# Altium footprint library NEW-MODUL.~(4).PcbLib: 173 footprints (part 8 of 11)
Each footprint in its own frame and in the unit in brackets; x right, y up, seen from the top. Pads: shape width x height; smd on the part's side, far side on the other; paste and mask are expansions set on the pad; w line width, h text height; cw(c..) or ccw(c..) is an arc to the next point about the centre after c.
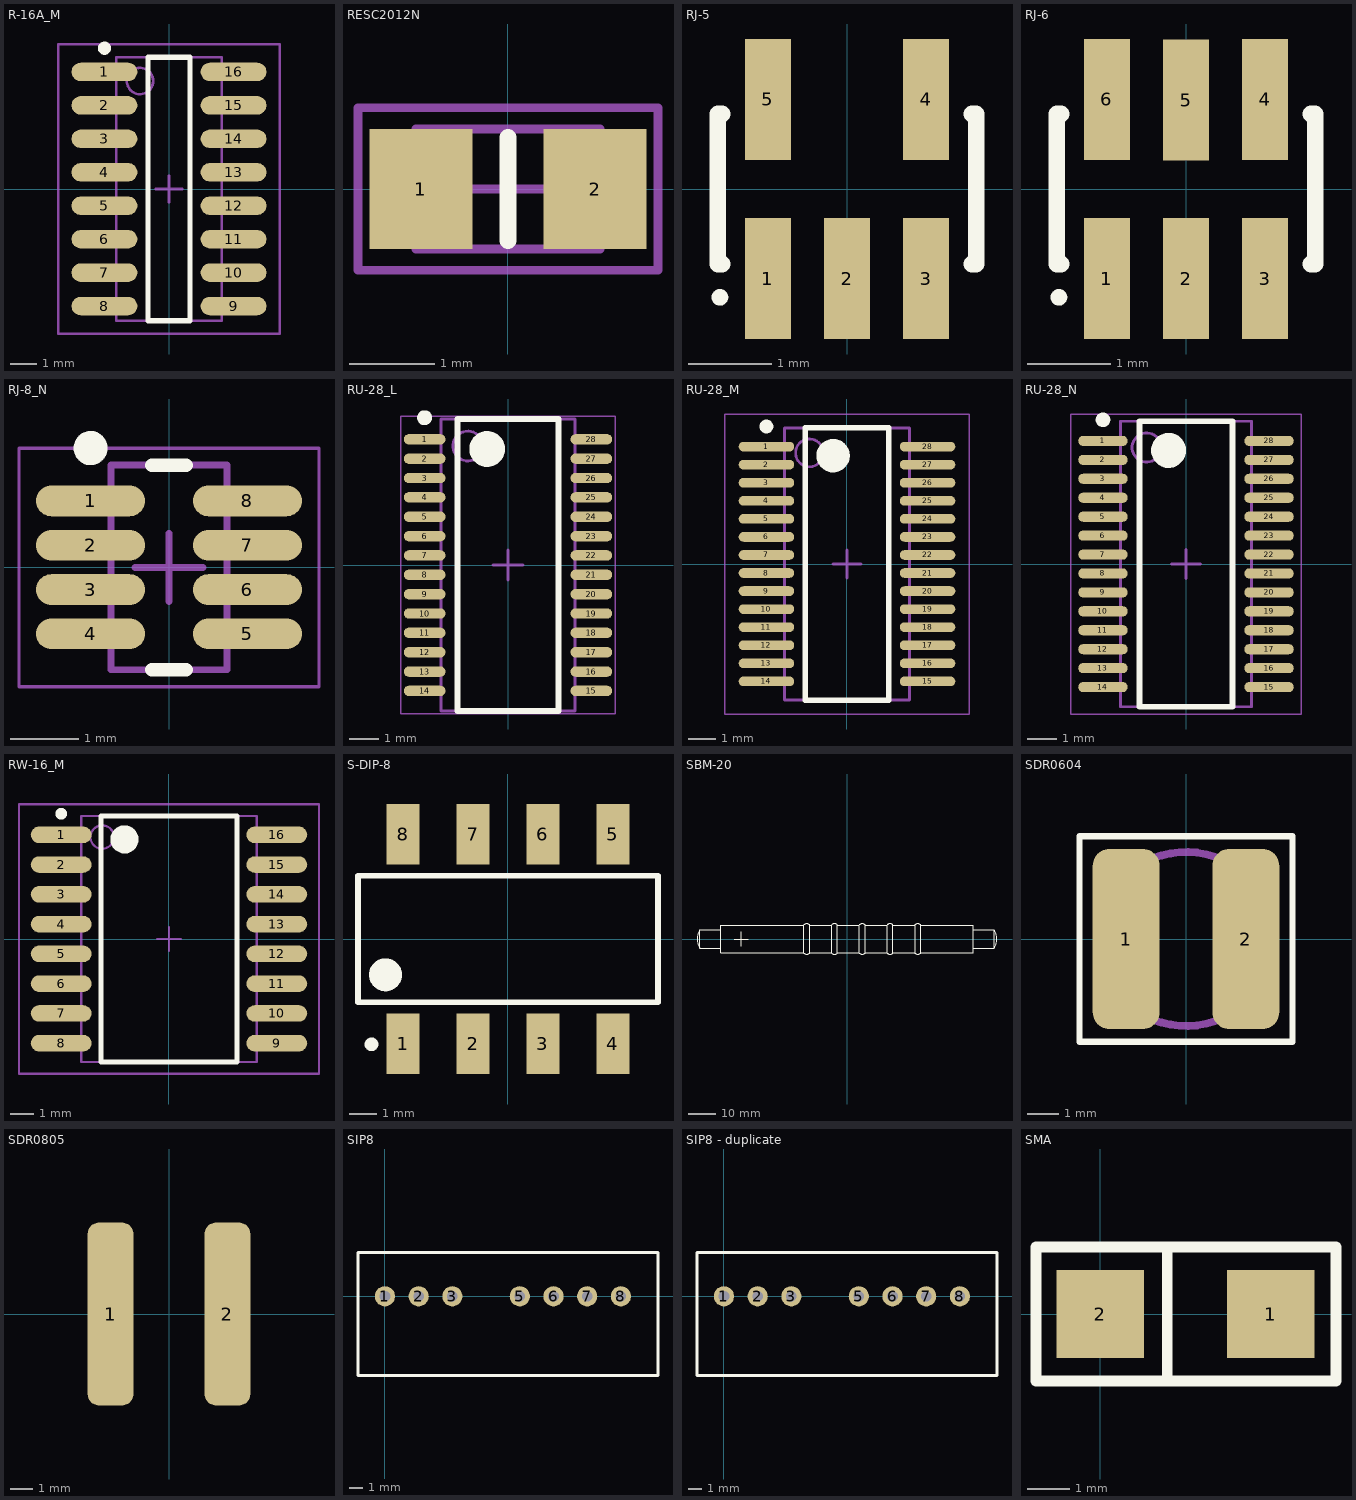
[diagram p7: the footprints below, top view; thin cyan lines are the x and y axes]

## R-16A_M [mm] "16-Pin Small Outline Integrated Circuit 1.27 mm Pitch, IPC Low Density"
height 1.75
pads (16):
  oval 2.5x0.7 smd: 1(-2.45,4.445) 2(-2.45,3.175) 3(-2.45,1.905) 4(-2.45,0.635) 5(-2.45,-0.635) 6(-2.45,-1.905) 7(-2.45,-3.175) 8(-2.45,-4.445) 9(2.45,-4.445) 10(2.45,-3.175) 11(2.45,-1.905) 12(2.45,-0.635) 13(2.45,0.635) 14(2.45,1.905) 15(2.45,3.175) 16(2.45,4.445)
Top Overlay:
  circle w0.25: c-2.45,5.345 r0.125
  lines w0.2: -0.8,-5 -0.8,5 0.8,5 0.8,-5 -0.8,-5
Mechanical 13:
  circle w0.1: c-1.1,4.1 r0.5
  lines w0.1: -2,-5 -2,5 2,5 2,-5 -2,-5
Mechanical 15:
  lines w0.1: -0.5,0 0.5,0 ; 0,-0.5 0,0.5 ; -4.2,-5.5 -4.2,5.5 4.2,5.5 4.2,-5.5 -4.2,-5.5
3D body "User Library-SOIC-16-2.step": height 1.75, standoff 0, extent -3,-5 3,5

## RESC2012N [mm] "Chip Resistor, Body 2.0x1.3mm, IPC Medium Density"
height 0.65
pads (2):
  rect 1.2x1.4 smd: 1(-1.016,0) 2(1.016,0)
Top Overlay:
  lines w0.2: 0,-0.6 0,0.6
Mechanical 13:
  lines w0.1: -1.075,-0.7 1.075,-0.7 1.075,0.7 -1.075,0.7 -1.075,-0.7
Mechanical 15:
  lines w0.1: -0.5,0 0.5,0 ; 0,-0.5 0,0.5 ; -1.75,-0.95 1.75,-0.95 1.75,0.95 -1.75,0.95 -1.75,-0.95
3D body "User Library-0805 SMD Resistor.step": height 0.78, standoff 0, extent -1,-0.625 1,0.625

## RJ-5 [mm] "SOT-23/SC-74A; 5 Leads; Body 3.1 x 3 mm, inc. leads (LxW max)"
height 1.45
pads (5):
  rect 0.55x1.45 smd: 1(-0.95,-1.075) 2(0,-1.075) 3(0.95,-1.075) 4(0.95,1.075) 5(-0.95,1.075)
Top Overlay:
  circle w0.1: c-1.525,-1.3 r0.05
  lines w0.2: -1.5,-0.9 -1.55,-0.9 -1.55,0.9 -1.5,0.9 ; 1.5,-0.9 1.55,-0.9 1.55,0.9 1.5,0.9

## RJ-6 [mm] "SOT-23/SC-74A; 6 Leads; Body 3.1 x 3 mm, inc. leads (LxW max)"
height 1.45
pads (6):
  rect 0.55x1.45 smd: 1(-0.95,-1.075) 2(0,-1.075) 3(0.95,-1.075) 4(0.95,1.075) 5(0,1.068) 6(-0.95,1.075)
Top Overlay:
  circle w0.1: c-1.525,-1.3 r0.05
  lines w0.2: -1.5,-0.9 -1.55,-0.9 -1.55,0.9 -1.5,0.9 ; 1.5,-0.9 1.55,-0.9 1.55,0.9 1.5,0.9
3D body "User Library-SOT23-6-2.step": height 1.45, standoff 0, extent -1.45,-1.4 1.45,1.4

## RJ-8_N [mm] "SOP, 8-Leads, Body 2.9x1.6mm, Pitch 0.65mm, IPC Medium Density"
height 1.45
pads (8):
  oval 1.6x0.45 smd: 1(-1.15,0.975) 2(-1.15,0.325) 3(-1.15,-0.325) 4(-1.15,-0.975) 5(1.15,-0.975) 6(1.15,-0.325) 7(1.15,0.325) 8(1.15,0.975)
Top Overlay:
  circle w0.25: c-1.15,1.75 r0.125
  lines w0.2: -0.25,-1.5 0.25,-1.5 ; -0.25,1.5 0.25,1.5
Mechanical 13:
  lines w0.1: -0.85,-1.5 -0.85,1.5 0.85,1.5 0.85,-1.5 -0.85,-1.5
Mechanical 15:
  lines w0.05: -2.2,-1.75 -2.2,1.75 2.2,1.75 2.2,-1.75 -2.2,-1.75
  lines w0.1: -0.5,0 0.5,0 ; 0,-0.5 0,0.5
3D body "User Library-sot238.step": height 1.2, standoff 0, extent -1.425,-1.495 1.375,1.445

## RU-28_L [mm] "TSOP, 28-Leads, Body 9.7x4.4mm, Pitch 0.65mm, IPC High Density"
height 1.2
pads (28):
  oval 1.4x0.35 smd: 1(-2.8,4.225) 2(-2.8,3.575) 3(-2.8,2.925) 4(-2.8,2.275) 5(-2.8,1.625) 6(-2.8,0.975) 7(-2.8,0.325) 8(-2.8,-0.325) 9(-2.8,-0.975) 10(-2.8,-1.625) 11(-2.8,-2.275) 12(-2.8,-2.925) 13(-2.8,-3.575) 14(-2.8,-4.225) 15(2.8,-4.225) 16(2.8,-3.575) 17(2.8,-2.925) 18(2.8,-2.275) 19(2.8,-1.625) 20(2.8,-0.975) 21(2.8,-0.325) 22(2.8,0.325) 23(2.8,0.975) 24(2.8,1.625) 25(2.8,2.275) 26(2.8,2.925) 27(2.8,3.575) 28(2.8,4.225)
Top Overlay:
  circle w0.25: c-2.8,4.95 r0.125
  circle w0.6: c-0.7,3.9 r0.3
  lines w0.2: -1.7,-4.9 -1.7,4.9 1.7,4.9 1.7,-4.9 -1.7,-4.9
Mechanical 13:
  circle w0.1: c-1.35,4 r0.5
  lines w0.1: -2.25,-4.9 -2.25,4.9 2.25,4.9 2.25,-4.9 -2.25,-4.9
Mechanical 15:
  lines w0.05: -3.6,-5 -3.6,5 3.6,5 3.6,-5 -3.6,-5
  lines w0.1: -0.5,0 0.5,0 ; 0,-0.5 0,0.5
3D body: height 1.2, standoff 0.05, extent -2.25,-4.9 2.25,4.9

## RU-28_M [mm] "TSOP, 28-Leads, Body 9.7x4.4mm, Pitch 0.65mm, IPC Low Density"
height 1.2
pads (28):
  oval 2x0.35 smd: 1(-2.9,4.225) 2(-2.9,3.575) 3(-2.9,2.925) 4(-2.9,2.275) 5(-2.9,1.625) 6(-2.9,0.975) 7(-2.9,0.325) 8(-2.9,-0.325) 9(-2.9,-0.975) 10(-2.9,-1.625) 11(-2.9,-2.275) 12(-2.9,-2.925) 13(-2.9,-3.575) 14(-2.9,-4.225) 15(2.9,-4.225) 16(2.9,-3.575) 17(2.9,-2.925) 18(2.9,-2.275) 19(2.9,-1.625) 20(2.9,-0.975) 21(2.9,-0.325) 22(2.9,0.325) 23(2.9,0.975) 24(2.9,1.625) 25(2.9,2.275) 26(2.9,2.925) 27(2.9,3.575) 28(2.9,4.225)
Top Overlay:
  circle w0.25: c-2.9,4.95 r0.125
  circle w0.6: c-0.5,3.9 r0.3
  lines w0.2: -1.5,-4.9 -1.5,4.9 1.5,4.9 1.5,-4.9 -1.5,-4.9
Mechanical 13:
  circle w0.1: c-1.35,4 r0.5
  lines w0.1: -2.25,-4.9 -2.25,4.9 2.25,4.9 2.25,-4.9 -2.25,-4.9
Mechanical 15:
  lines w0.05: -4.4,-5.4 -4.4,5.4 4.4,5.4 4.4,-5.4 -4.4,-5.4
  lines w0.1: -0.5,0 0.5,0 ; 0,-0.5 0,0.5
3D body "SW3dPS-TSSOP-28_P065.STEP": height 1.09, standoff 0.01, extent -3.206,-4.85 3.207,4.85

## RU-28_N [mm] "TSOP, 28-Leads, Body 9.7x4.4mm, Pitch 0.65mm, IPC Medium Density"
height 1.2
pads (28):
  oval 1.7x0.35 smd: 1(-2.85,4.225) 2(-2.85,3.575) 3(-2.85,2.925) 4(-2.85,2.275) 5(-2.85,1.625) 6(-2.85,0.975) 7(-2.85,0.325) 8(-2.85,-0.325) 9(-2.85,-0.975) 10(-2.85,-1.625) 11(-2.85,-2.275) 12(-2.85,-2.925) 13(-2.85,-3.575) 14(-2.85,-4.225) 15(2.85,-4.225) 16(2.85,-3.575) 17(2.85,-2.925) 18(2.85,-2.275) 19(2.85,-1.625) 20(2.85,-0.975) 21(2.85,-0.325) 22(2.85,0.325) 23(2.85,0.975) 24(2.85,1.625) 25(2.85,2.275) 26(2.85,2.925) 27(2.85,3.575) 28(2.85,4.225)
Top Overlay:
  circle w0.25: c-2.85,4.95 r0.125
  circle w0.6: c-0.6,3.9 r0.3
  lines w0.2: -1.6,-4.9 -1.6,4.9 1.6,4.9 1.6,-4.9 -1.6,-4.9
Mechanical 13:
  circle w0.1: c-1.35,4 r0.5
  lines w0.1: -2.25,-4.9 -2.25,4.9 2.25,4.9 2.25,-4.9 -2.25,-4.9
Mechanical 15:
  lines w0.05: -3.95,-5.15 -3.95,5.15 3.95,5.15 3.95,-5.15 -3.95,-5.15
  lines w0.1: -0.5,0 0.5,0 ; 0,-0.5 0,0.5
3D body: height 1.2, standoff 0.05, extent -2.25,-4.9 2.25,4.9

## RW-16_M [mm] "16-Pin Wide Body Small Outline Integrated Circuit 1.27 mm Pitch, IPC Low Density"
height 2.65
pads (16):
  oval 2.6x0.7 smd: 1(-4.6,4.445) 2(-4.6,3.175) 3(-4.6,1.905) 4(-4.6,0.635) 5(-4.6,-0.635) 6(-4.6,-1.905) 7(-4.6,-3.175) 8(-4.6,-4.445) 9(4.6,-4.445) 10(4.6,-3.175) 11(4.6,-1.905) 12(4.6,-0.635) 13(4.6,0.635) 14(4.6,1.905) 15(4.6,3.175) 16(4.6,4.445)
Top Overlay:
  circle w0.25: c-4.6,5.345 r0.125
  circle w0.6: c-1.9,4.25 r0.3
  lines w0.2: -2.9,-5.25 -2.9,5.25 2.9,5.25 2.9,-5.25 -2.9,-5.25
Mechanical 13:
  circle w0.1: c-2.85,4.35 r0.5
  lines w0.1: -3.75,-5.25 -3.75,5.25 3.75,5.25 3.75,-5.25 -3.75,-5.25
Mechanical 15:
  lines w0.1: -0.5,0 0.5,0 ; 0,-0.5 0,0.5 ; -6.4,-5.75 -6.4,5.75 6.4,5.75 6.4,-5.75 -6.4,-5.75
3D body "User Library-141x.step": height 2.5, standoff 0, extent -5.25,-5.25 5.25,5.25

## S-DIP-8 [mm] "DIP; 8 Trim Leads; Row Spacing 7.62 mm; Pitch 2.54 mm"
height 5.58
pads (8):
  rect 1.2x2.2 smd: 1(-3.81,-3.8) 2(-1.27,-3.8) 3(1.27,-3.8) 4(3.81,-3.8) 5(3.81,3.8) 6(1.27,3.8) 7(-1.27,3.8) 8(-3.81,3.8)
Top Overlay:
  circle w0.25: c-4.96,-3.827 r0.125
  circle w0.6: c-4.45,-1.3 r0.3
  lines w0.2: -5.45,-2.3 -5.45,2.3 5.45,2.3 5.45,-2.3 -5.45,-2.3
3D body "User Library-8-pin-DIP_GW_HCPL-4200-300E.step": height 4.34, standoff 0.02, extent -4.965,-4.914 4.935,4.986

## SBM-20 [mm]
Top Overlay:
  lines w0.254: -52.965,-3.221 cw(c-48.5,0) -52.965,3.221 ; -40.64,0 -35.56,0 ; -38.1,-2.54 -38.1,2.54 ; -15.561,-5.061 ccw(c-14.5,-4) -13.439,-5.061 ; -15.561,5.061 cw(c-14.5,4) -13.439,5.061 ; -5.561,-5.061 ccw(c-4.5,-4) -3.439,-5.061 ; -5.561,5.061 cw(c-4.5,4) -3.439,5.061 ; 4.439,-5.061 ccw(c5.5,-4) 6.561,-5.061 ; 4.439,5.061 cw(c5.5,4) 6.561,5.061 ; 14.439,-5.061 ccw(c15.5,-4) 16.561,-5.061 ; 14.439,5.061 cw(c15.5,4) 16.561,5.061 ; 24.439,-5.061 ccw(c25.5,-4) 26.561,-5.061 ; 24.439,5.061 cw(c25.5,4) 26.561,5.061 ; 52.965,-3.221 ccw(c48.5,0) 52.965,3.221 ; -45.5,-3.25 -53,-3.25 -53,0 -53,3.25 -45.5,3.25 ; -45.5,-3.25 -45.5,3.25 ; -45.5,-3.25 -45.5,-5 -15.5,-5 -15.5,5 -45.5,5 -45.5,3.25 ; -3.5,-5 4.5,-5 ; -3.5,-5 4.5,-5 ; -3.5,-5 -3.5,5 ; -3.5,5 4.5,5 ; -3.5,5 4.5,5 ; 4.5,-5 4.5,5 ; 6.5,-5 14.5,-5 ; 6.5,-5 14.5,-5 ; 6.5,-5 6.5,5 ; 6.5,5 14.5,5 ; 6.5,5 14.5,5 ; 14.5,-5 14.5,5 ; -13.5,-5 -5.5,-5 -5.5,5 -13.5,5 -13.5,-5 ; 16.5,-5 24.5,-5 24.5,5 16.5,5 16.5,-5 ; 26.5,-5 45.5,-5 45.5,5 26.5,5 26.5,-5 ; 45.5,-3.25 53,-3.25 53,3.25 45.5,3.25 45.5,0 45.5,-3.25
3D body "SBM20GMtube.stp": height 10.29, standoff -0.34, extent -53.442,-5.008 53.467,5.639

## SDR0604 [mm]
pads (2):
  rrect50% 2.15x5.8 smd: 1(-1.925,0) 2(1.925,0)
Top Overlay:
  lines w0.2: -3.429,-3.302 3.429,-3.302 3.429,3.302 -3.429,3.302 -3.429,-0.829 -3.429,-3.302
Mechanical 1:
  circle w0.254: c0,0 r2.8
3D body "User Library-SDR0604.step": height 4.55, standoff 0, extent -2.754,-2.8 2.754,2.8

## SDR0805 [mm]
pads (2):
  rrect50% 2x8 smd: 1(-2.55,0) 2(2.55,0)
3D body "User Library-SR0805-1.step": height 5.01, standoff 0, extent -3.75,-4 3.75,3.479

## SIP8 [mil]
pads (7):
  round 60 hole 31.5: 1(0,0) 2(100,0) 3(200,0) 5(400,0) 6(500,0) 7(600,0) 8(700,0)
Top Overlay:
  lines w10: -80,-235 810,-235 810,130 -80,130 -80,-235
3D body "User Library-TRACO TMR.step": height 382.49, standoff -156.88, extent -80,-288.68 778.27,128.68

## SIP8 - duplicate [mil]
pads (7):
  round 60 hole 31.5: 1(0,0) 2(100,0) 3(200,0) 5(400,0) 6(500,0) 7(600,0) 8(700,0)
Top Overlay:
  lines w10: -80,-235 810,-235 810,130 -80,130 -80,-235
3D body "User Library-TRACO TMR.step": height 382.49, standoff -156.88, extent -80,-288.68 778.27,128.68

## SMA [mil]
pads (2):
  rect 82x82 smd: 1(159.06,0) 2(0,0)
Top Overlay:
  lines w10: 62.5,-62.5 -60,-62.5 -60,62.5 62.5,62.5 ; 62.5,-62.5 62.5,62.5 ; 62.5,-62.5 220,-62.5 220,62.5 62.5,62.5
3D body "User Library-DO-214AC(SMA)(1).step": height 90.6, standoff 0.6, extent -28,-55 188,55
